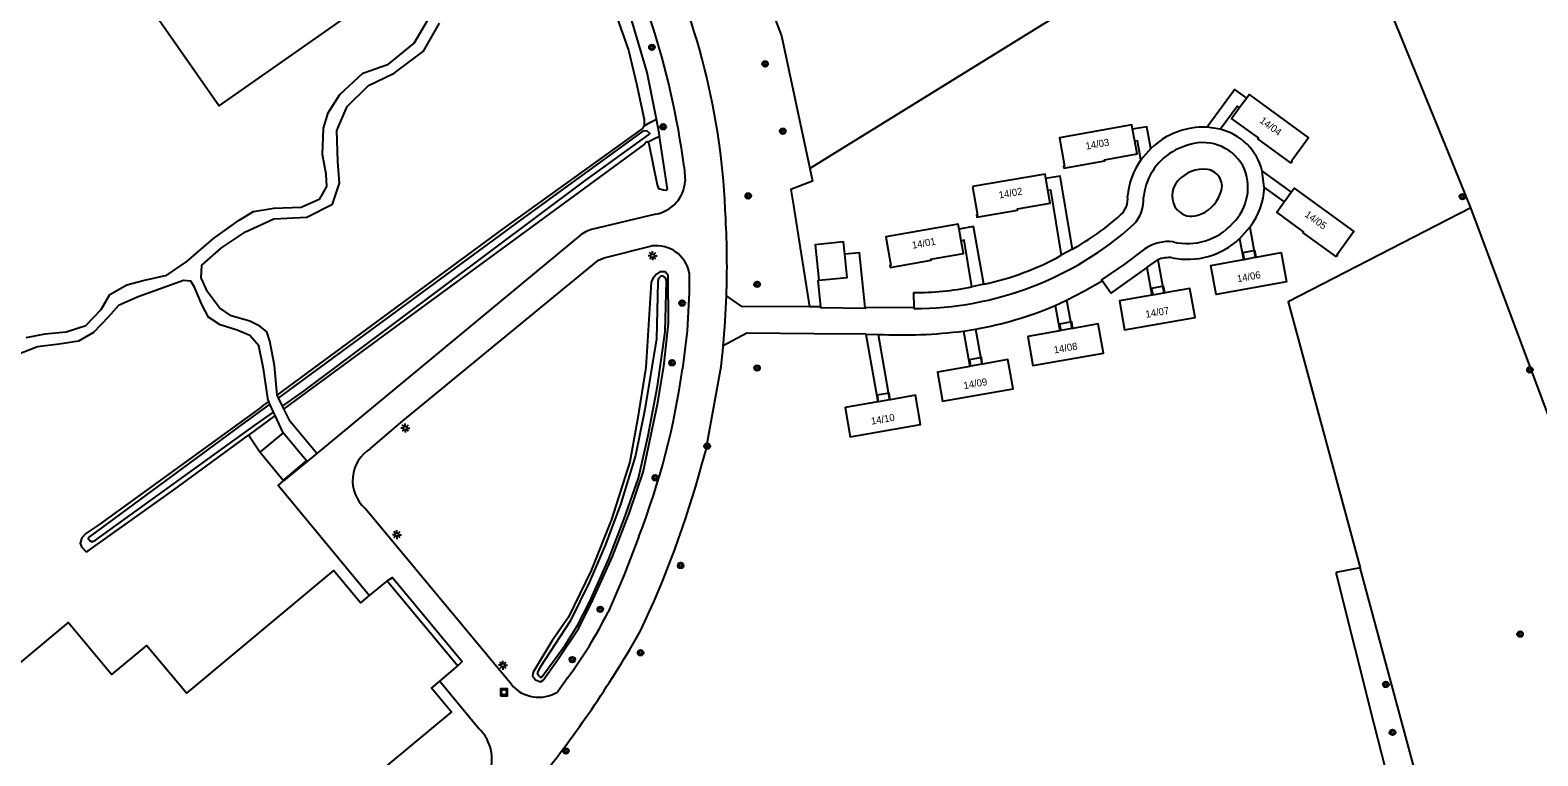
# Model space of a CAD drawing. Extents: x 141000 to 143000, y 400580 to 403500.
# Drawn here: x 141206 to 141417.1, y 402812.9 to 402914.6 of the extents above; entities that cross this region are included whole.
import ezdxf

# ---------------------------------------------------------------- set-up
doc = ezdxf.new("R2010")
doc.units = 0
for name, color, linetype in [('gg-afsc-erfafscheiding', 7, 'Continuous'), ('gg-anno-huisnummerreeks BGT', 7, 'Continuous'), ('gg-bbg-bijgebouw', 7, 'Continuous'), ('gg-bbg-gedigitaliseerde bijgebouw', 7, 'Continuous'), ('gg-bbg-hoofdgebouw', 7, 'Continuous'), ('gg-bbg-luifel en loopbrug', 7, 'Continuous'), ('gg-knt-bronhoudergrens', 7, 'Continuous'), ('gg-knt-onverhard', 7, 'Continuous'), ('gg-knt-verharding', 7, 'Continuous'), ('gg-knt-verharding nz', 7, 'Continuous'), ('gg-kntw-bovenkant insteek waterloop', 7, 'Continuous'), ('gg-kntw-waterlijn', 7, 'Continuous'), ('gt-grn-groengrens', 7, 'Continuous'), ('gt-symb-boom', 7, 'Continuous'), ('gt-symb-lichtmast', 7, 'Continuous'), ('gt-symb-rioolschacht', 7, 'Continuous')]:
    doc.layers.add(name, color=color, linetype=linetype)

# ---------------------------------------------------------------- blocks, each defined once
blk = doc.blocks.new('gt0-BOOM')
at = {"layer": 'gt-symb-boom'}
for radius in [0.4, 0.2]:
    blk.add_circle((0, 0), radius, dxfattribs=at)
blk = doc.blocks.new('gt0-LMAST')
at = {"layer": 'gt-symb-lichtmast'}
for p, q in [((-0.18, 0.17), (-0.45, 0.44)), ((-0.01, 0.25), (-0.01, 0.62)), ((0.17, 0.17), (0.44, 0.44)), ((-0.26, 0), (-0.63, 0)), ((-0.18, -0.18), (-0.45, -0.45)), ((-0.01, -0.25), (-0.01, -0.63)), ((0.44, -0.45), (0.17, -0.18)), ((0.24, 0), (0.62, 0))]:
    blk.add_line(p, q, dxfattribs=at)
blk.add_circle((-0.01, 0), 0.25, dxfattribs=at)
blk = doc.blocks.new('gt0-RS')
at = {"layer": 'gt-symb-rioolschacht'}
blk.add_lwpolyline([(-0.5, -0.5), (0.5, -0.5), (0.5, 0.5), (-0.5, 0.5)], close=True, dxfattribs=at)
blk.add_circle((0, 0), 0.375, dxfattribs=at)

msp = doc.modelspace()

# ---------------------------------------------------------------- linework, layer by layer
at = {"layer": 'gg-afsc-erfafscheiding'}
msp.add_line((141241.49, 402851.46), (141241.44, 402851.52), dxfattribs=at)
at = {"layer": 'gg-bbg-bijgebouw'}
for points in [[(141320.08, 402883.22), (141319.9, 402884.94), (141315.94, 402884.53), (141316.46, 402879.57)], [(141316.46, 402879.57), (141320.42, 402879.98), (141320.08, 402883.22)]]:
    msp.add_lwpolyline(points, dxfattribs=at)
at = {"layer": 'gg-bbg-gedigitaliseerde bijgebouw'}
for p in [(141241.42, 402858.2), (141241.44, 402851.52)]:
    msp.add_line(p, (141238.15, 402855.47), dxfattribs=at)
msp.add_lwpolyline([(141241.44, 402851.52), (141244.72, 402854.25), (141241.42, 402858.2)], dxfattribs=at)
at = {"layer": 'gg-bbg-hoofdgebouw'}
for p, q in [((141375.33, 402903.73), (141376.33, 402905.1)), ((141360.69, 402899.06), (141360.39, 402900.73)), ((141348.52, 402892.19), (141348.24, 402893.83)), ((141381.63, 402890.55), (141382.61, 402891.9)), ((141336.39, 402885.1), (141336.09, 402886.75)), ((141375.91, 402882.49), (141376, 402882.5)), ((141376, 402882.5), (141377.57, 402882.79)), ((141377.57, 402882.79), (141377.68, 402882.81)), ((141363.2, 402877.51), (141363.06, 402877.49)), ((141363.2, 402877.51), (141364.74, 402877.79)), ((141364.74, 402877.79), (141364.88, 402877.81)), ((141350.33, 402872.52), (141350.18, 402872.49)), ((141351.87, 402872.8), (141350.33, 402872.52)), ((141352.02, 402872.82), (141351.87, 402872.8)), ((141337.7, 402867.52), (141337.6, 402867.51)), ((141339.26, 402867.8), (141337.7, 402867.52)), ((141339.38, 402867.82), (141339.26, 402867.8)), ((141324.76, 402862.54), (141324.7, 402862.53)), ((141326.36, 402862.82), (141324.76, 402862.54)), ((141326.45, 402862.84), (141326.36, 402862.82)), ((141256, 402837.47), (141253.46, 402835.38)), ((141256, 402837.47), (141265.92, 402825.53)), ((141263.36, 402823.38), (141265.92, 402825.53))]:
    msp.add_line(p, q, dxfattribs=at)
for points in [[(141376.33, 402905.1), (141376.71, 402905.62), (141385.03, 402899.55), (141382.64, 402896.26), (141382.74, 402896.19), (141382.6, 402895.98)], [(141382.6, 402895.98), (141377.92, 402899.41), (141378.01, 402899.53), (141374.26, 402902.26), (141375.33, 402903.73)], [(141360.39, 402900.73), (141360.27, 402901.37), (141350.13, 402899.55), (141350.85, 402895.55), (141350.72, 402895.53), (141350.77, 402895.28)], [(141350.77, 402895.28), (141356.48, 402896.31), (141356.45, 402896.45), (141361.01, 402897.28), (141360.69, 402899.06)], [(141348.24, 402893.83), (141348.13, 402894.46), (141337.97, 402892.7)], [(141337.97, 402892.7), (141338.65, 402888.7), (141338.53, 402888.68), (141338.57, 402888.43), (141344.29, 402889.42), (141344.27, 402889.57), (141348.83, 402890.36), (141348.52, 402892.19)], [(141382.61, 402891.9), (141383.02, 402892.46), (141391.35, 402886.41), (141388.98, 402883.11), (141389.08, 402883.04), (141388.93, 402882.84)], [(141388.93, 402882.84), (141384.24, 402886.26), (141384.33, 402886.38), (141380.58, 402889.1), (141381.63, 402890.55)], [(141336.09, 402886.75), (141335.97, 402887.44), (141325.83, 402885.65), (141326.53, 402881.65), (141326.41, 402881.63), (141326.45, 402881.38)], [(141326.45, 402881.38), (141332.16, 402882.4), (141332.13, 402882.54), (141336.7, 402883.34), (141336.39, 402885.1)], [(141377.68, 402882.81), (141381.21, 402883.45), (141381.95, 402879.36), (141372.09, 402877.58), (141371.36, 402881.66), (141375.91, 402882.49)], [(141363.06, 402877.49), (141358.55, 402876.69), (141359.27, 402872.61), (141369.14, 402874.35), (141368.42, 402878.43), (141364.88, 402877.81)], [(141350.18, 402872.49), (141345.71, 402871.7), (141346.43, 402867.61), (141356.29, 402869.36), (141355.56, 402873.46), (141352.02, 402872.82)], [(141337.6, 402867.51), (141333.07, 402866.7), (141333.79, 402862.61), (141343.65, 402864.37), (141342.92, 402868.45), (141339.38, 402867.82)], [(141324.7, 402862.53), (141320.12, 402861.73), (141320.84, 402857.64), (141330.7, 402859.36), (141329.98, 402863.46), (141326.45, 402862.84)], [(141253.46, 402835.38), (141252.26, 402834.38), (141248.5, 402838.88), (141227.88, 402821.7), (141222.3, 402828.38), (141217.42, 402824.34), (141211.33, 402831.63), (141190.16, 402813.95), (141190.17, 402813.93)], [(141232.74, 402805.73), (141239.4, 402797.73), (141265, 402819.06), (141262.19, 402822.41), (141263.36, 402823.38)]]:
    msp.add_lwpolyline(points, dxfattribs=at)
at = {"layer": 'gg-bbg-luifel en loopbrug'}
for points in [[(141377.68, 402882.81), (141377.52, 402883.74), (141375.84, 402883.42), (141376, 402882.5)], [(141364.88, 402877.81), (141364.72, 402878.73), (141363.03, 402878.44), (141363.2, 402877.51)], [(141352.02, 402872.82), (141351.86, 402873.75), (141350.17, 402873.44), (141350.33, 402872.52)], [(141339.38, 402867.82), (141339.22, 402868.75), (141337.54, 402868.44), (141337.7, 402867.52)], [(141326.45, 402862.84), (141326.29, 402863.76), (141324.6, 402863.47), (141324.76, 402862.54)]]:
    msp.add_lwpolyline(points, dxfattribs=at)
at = {"layer": 'gg-knt-bronhoudergrens'}
for p, q in [((141404.66, 402897.35), (141387.07, 402940.44)), ((141407.77, 402889.73), (141404.66, 402897.35)), ((141409.82, 402774.28), (141392.26, 402839.26))]:
    msp.add_line(p, q, dxfattribs=at)
for points in [[(141296.65, 402946.16), (141298.25, 402943.84), (141304.41, 402931.66), (141311.24, 402913.82), (141315.18, 402895.24)], [(141386.16, 402940.68), (141374.83, 402932.2), (141315.18, 402895.24)], [(141312.89, 402890.03), (141312.98, 402889.45), (141315.14, 402875.85)], [(141407.77, 402889.73), (141382.18, 402876.56), (141392.26, 402839.26)], [(141432.62, 402827.07), (141427.58, 402836.55), (141407.77, 402889.73)]]:
    msp.add_lwpolyline(points, dxfattribs=at)
at = {"layer": 'gg-knt-onverhard'}
for p, q in [((141300.61, 402855.69), (141302.78, 402867.51)), ((141392.26, 402839.26), (141388.85, 402838.6))]:
    msp.add_line(p, q, dxfattribs=at)
at = {"layer": 'gg-knt-verharding'}
for p, q in [((141372.67, 402900.73), (141370.8, 402901.04)), ((141362.95, 402898.03), (141361.54, 402896.44)), ((141297.57, 402895.47), (141297.74, 402893.47)), ((141378.52, 402894.87), (141382.61, 402891.9)), ((141378.83, 402892.58), (141378.52, 402894.87)), ((141378.83, 402892.58), (141381.63, 402890.55)), ((141375.38, 402885.4), (141376.8, 402887.02)), ((141376.8, 402887.02), (141377.57, 402882.79)), ((141351.99, 402883.95), (141350.4, 402883.08)), ((141375.38, 402885.4), (141375.91, 402882.49)), ((141362.37, 402881.36), (141363.92, 402882.43)), ((141363.92, 402882.43), (141364.74, 402877.79)), ((141362.37, 402881.36), (141363.06, 402877.49)), ((141329.69, 402877.85), (141329.76, 402875.73)), ((141339.54, 402879.02), (141337.89, 402878.65)), ((141316.75, 402875.84), (141315.14, 402875.85)), ((141329.76, 402875.73), (141322.96, 402875.76)), ((141329.76, 402875.61), (141329.76, 402875.73)), ((141349.54, 402876.03), (141350.18, 402872.49)), ((141351.15, 402876.78), (141351.87, 402872.8)), ((141323.04, 402872), (141315.74, 402872.08)), ((141323.04, 402872), (141324.7, 402862.53)), ((141324.75, 402871.99), (141326.36, 402862.82)), ((141336.72, 402872.45), (141337.6, 402867.51)), ((141338.38, 402872.73), (141339.26, 402867.8)), ((141302.78, 402867.51), (141302.95, 402869.27)), ((141239.58, 402862.23), (141239.42, 402862.57)), ((141240.79, 402863.12), (141240.62, 402863.46)), ((141241.35, 402861.95), (141240.79, 402863.12)), ((141240.1, 402861.09), (141239.58, 402862.23)), ((141240.31, 402860.63), (141240.1, 402861.09)), ((141241.42, 402858.2), (141240.31, 402860.63)), ((141241.55, 402861.54), (141241.35, 402861.95)), ((141238.15, 402855.47), (141236.57, 402857.87)), ((141246.13, 402855.3), (141241.49, 402851.46)), ((141300.08, 402853.75), (141300.61, 402855.69)), ((141273.39, 402822.91), (141252.91, 402847.61)), ((141263.36, 402823.38), (141268.9, 402816.72)), ((141281.3, 402823.9), (141279.86, 402821.86))]:
    msp.add_line(p, q, dxfattribs=at)
for points in [[(141205.43, 402871.57), (141208.12, 402872.05), (141211.06, 402872.34), (141213.81, 402873.25), (141215.93, 402875.47), (141217.18, 402877.59), (141219.54, 402878.94), (141221.85, 402879.52), (141225.13, 402880.29), (141227.97, 402882.21), (141231.68, 402885.44), (141235.29, 402887.99), (141237.27, 402889.2), (141240.11, 402889.68), (141243.96, 402889.82), (141246.56, 402890.98), (141247.53, 402892.71), (141247.48, 402894.45), (141246.95, 402897.19), (141247.09, 402900.9), (141247.72, 402903.02), (141249.36, 402905.62), (141252.58, 402908.61), (141256.2, 402909.86), (141259.76, 402912.8), (141261.78, 402916.22)], [(141240.62, 402863.46), (141240.21, 402867.61), (141239.59, 402871.06), (141239.13, 402872.35), (141238.16, 402873.13), (141236.75, 402873.84), (141234.15, 402874.57), (141232.52, 402875.72), (141230.84, 402877.94), (141229.96, 402879.92), (141230.03, 402881.7), (141232.82, 402884.14), (141236.16, 402886.37), (141240.15, 402888.2), (141244.73, 402888.41), (141248.36, 402890.24), (141249.32, 402893.18), (141249.07, 402896.24), (141248.94, 402900.58), (141250.4, 402903.92), (141253.4, 402906.86), (141256.96, 402908.59), (141261.11, 402911.66), (141263.34, 402915.62)], [(141370.8, 402901.04), (141374.66, 402906.31), (141376.33, 402905.1)], [(141372.67, 402900.73), (141375.01, 402903.96), (141375.33, 402903.73)], [(141362.95, 402898.03), (141362.39, 402901.08), (141360.39, 402900.73)], [(141361.54, 402896.44), (141361.08, 402899.13), (141360.69, 402899.06)], [(141351.99, 402883.95), (141350.26, 402894.18), (141348.24, 402893.83)], [(141348.52, 402892.19), (141348.88, 402892.25), (141350.4, 402883.08)], [(141362.28, 402893.01), (141362.04, 402892.04), (141361.93, 402891.24)], [(141293.63, 402888.85), (141284.61, 402886.71), (141283.87, 402886.41), (141283.19, 402885.99), (141246.13, 402855.3)], [(141339.54, 402879.02), (141338.11, 402887.11), (141336.09, 402886.75)], [(141253.67, 402855.98), (141257.91, 402859.65), (141285.61, 402882.37), (141286.37, 402882.74), (141293.08, 402884.38)], [(141337.89, 402878.65), (141336.78, 402885.17), (141336.39, 402885.1)], [(141362.12, 402884), (141359.27, 402881.84), (141356.05, 402879.62), (141356.13, 402879.5)], [(141322.96, 402875.76), (141322.16, 402883.43), (141320.08, 402883.22)], [(141239.42, 402862.57), (141239.34, 402862.74), (141238.69, 402867.15), (141238.02, 402870.38), (141236.75, 402871.85), (141234.98, 402872.58), (141232.62, 402873.34), (141230.97, 402874.42), (141230.05, 402876.19), (141229.01, 402878.6), (141228.49, 402879.43), (141227.5, 402879.54), (141221.12, 402877.26), (141218.4, 402876.05), (141216.92, 402874.42), (141214.9, 402872.24), (141212.76, 402871.05), (141210.05, 402870.62), (141207.05, 402870.26), (141204.04, 402869.07)], [(141298.3, 402880.62), (141298.28, 402877.86), (141298, 402872.5), (141297.38, 402867.16)], [(141316.75, 402875.84), (141316.36, 402879.56), (141316.46, 402879.57)], [(141351.15, 402876.78), (141353.66, 402878.11), (141356.13, 402879.5)], [(141362.37, 402881.36), (141357.33, 402877.75), (141356.13, 402879.5)], [(141315.14, 402875.85), (141305.68, 402875.92), (141303.51, 402877.38)], [(141315.74, 402872.08), (141306.37, 402872.18), (141303.06, 402870.38)], [(141246.13, 402855.3), (141242.4, 402859.79), (141241.55, 402861.54)], [(141253.46, 402835.38), (141240.73, 402850.83), (141241.49, 402851.46)], [(141291.26, 402843.65), (141289.2, 402838.31), (141286.93, 402833.07)], [(141256, 402837.47), (141256.74, 402837.92), (141266.52, 402826.15), (141265.92, 402825.53)]]:
    msp.add_lwpolyline(points, dxfattribs=at)
for centre, radius, start, end in [((141203.51, 402884.91), 99.95, 1.8735, 26.3315), ((141185.61, 402880.89), 112.91, 7.4198, 18.0776), ((141370.39, 402890.36), 10.69, 87.7956, 134.1768), ((141370.8, 402893.01), 7.94, 13.5723, 76.3983), ((141370.2, 402892.34), 6.53, 30.3583, 111.4062), ((141370.38, 402890.33), 10.75, 145.3573, 174.5935), ((141370.33, 402890.31), 8.48, 107.2125, 161.4894), ((141370.29, 402890.42), 4.7, 82.8315, 139.1211), ((141370.57, 402892.77), 2.34, 331.851, 82.5055), ((141369.54, 402892.59), 7, 313.8438, 25.8084), ((141292.73, 402893.79), 5.02, 280.3478, 356.3667), ((141369.01, 402891.41), 3.09, 137.53, 220.2784), ((141368.85, 402893.08), 10, 322.7146, 357.1256), ((141356.82, 402890.93), 2.88, 310.381, 8.2281), ((141356.85, 402890.91), 5.09, 316.1006, 3.6949), ((141368.17, 402893.21), 4.72, 286.7499, 340.8742), ((141184.09, 402881.54), 119.5, 358.0049, 3.1838), ((141335.27, 402914.47), 34.8, 298.7119, 312.3036), ((141368.62, 402891.14), 2.61, 221.2053, 290.3381), ((141329.82, 402921.53), 45.92, 269.9285, 311.9622), ((141368.04, 402893.23), 8.52, 256.6734, 318.1453), ((141293.69, 402879.72), 4.7, 11.0397, 97.4045), ((141365.32, 402879.33), 5.66, 82.2797, 124.4335), ((141368.05, 402893.23), 10.72, 258.6424, 313.1346), ((141331.51, 402917.05), 38.87, 281.9251, 299.0701), ((141365.45, 402878.92), 3.83, 82.6033, 113.474), ((141185.15, 402881.5), 118.43, 354.6093, 358.0048), ((141330.08, 402916.26), 38.41, 269.4172, 281.737), ((141329.7, 402922.6), 50.62, 279.8715, 293.0792), ((141328, 402943.25), 71.34, 267.3911, 277.0211), ((141196.4, 402880.32), 107.13, 354.0791, 354.674), ((141191.02, 402882.28), 107.42, 338.9227, 351.9101), ((141256.39, 402851.51), 5.23, 121.271, 228.2982), ((141164.12, 402890.65), 140.88, 334.6614, 344.8114), ((141230.79, 402861.23), 62.81, 323.5377, 333.3638), ((141153.37, 402909.18), 158.99, 321.5784, 330.2828), ((141277.25, 402826.21), 5.07, 220.5638, 300.9945), ((141264.62, 402812.45), 6.05, 31.9733, 44.8992), ((141264.63, 402812.46), 6.03, 317.9723, 31.9761)]:
    msp.add_arc(centre, radius, start, end, dxfattribs=at)
at = {"layer": 'gg-knt-verharding nz'}
for p, q in [((141349.54, 402876.03), (141351.15, 402876.78)), ((141323.04, 402872), (141324.75, 402871.99)), ((141336.72, 402872.45), (141338.38, 402872.73))]:
    msp.add_line(p, q, dxfattribs=at)
msp.add_lwpolyline([(141322.96, 402875.76), (141322.95, 402875.64), (141316.75, 402875.72), (141316.75, 402875.84)], dxfattribs=at)
at = {"layer": 'gg-kntw-bovenkant insteek waterloop'}
for p, q in [((141238.38, 402861.8), (141239.42, 402862.57)), ((141240.31, 402860.63), (141236.57, 402857.87))]:
    msp.add_line(p, q, dxfattribs=at)
for points in [[(141293.7, 402902.15), (141292.42, 402908.67), (141289.74, 402917.71), (141283.71, 402930.5), (141282.53, 402933.17)], [(141280.92, 402931.17), (141286.21, 402920.81), (141288.18, 402916.46), (141289.81, 402911.82), (141290.94, 402906.92), (141291.99, 402902.11), (141292, 402901.23)], [(141240.62, 402863.46), (141272.25, 402886.76), (141291.81, 402900.83), (141292, 402901.23)], [(141294.15, 402899.73), (141294.08, 402900.21), (141293.7, 402902.15)], [(141292.54, 402898.94), (141292.44, 402898.96), (141292.27, 402898.92), (141292.06, 402898.64), (141259.3, 402874.63), (141241.55, 402861.54)], [(141292.54, 402898.94), (141292.65, 402898.67), (141293.83, 402892.93), (141293.98, 402892.45), (141294.72, 402892.23), (141295.12, 402892.21), (141295.28, 402892.34), (141294.15, 402899.73)], [(141284.85, 402834.87), (141287.54, 402840.86), (141289.93, 402847.05), (141291.85, 402852.69), (141293.85, 402862.22), (141294.76, 402867.48), (141295.42, 402873.57), (141295.35, 402880.25), (141294.92, 402880.77), (141294.2, 402880.75), (141293.71, 402880.41), (141293.2, 402879.82), (141292.99, 402879.31), (141292.24, 402867.34), (141291.07, 402860.05), (141289.96, 402854.12), (141287.4, 402846.05), (141284.59, 402838.91), (141281.39, 402832.38), (141279.08, 402829), (141276.46, 402824.67), (141276.33, 402824.14), (141276.76, 402823.57), (141277.46, 402823.28), (141277.87, 402823.54), (141279.83, 402826.27), (141282.84, 402830.83), (141284.85, 402834.87)], [(141238.38, 402861.8), (141237.81, 402861.38), (141215.63, 402845.32), (141214.65, 402844.66)], [(141214.65, 402844.66), (141213.8, 402844.09), (141213.23, 402843.49), (141213, 402842.74), (141213.2, 402842.21), (141213.86, 402841.54), (141214.13, 402841.65), (141226.14, 402850.19), (141236.57, 402857.87)]]:
    msp.add_lwpolyline(points, dxfattribs=at)
at = {"layer": 'gg-kntw-waterlijn'}
for points in [[(141292, 402901.23), (141292.89, 402901.71), (141293.7, 402902.15)], [(141292.61, 402899.96), (141292.77, 402900.12), (141292.35, 402900.53), (141291.79, 402900.46), (141274.72, 402888.04), (141240.79, 402863.12)], [(141241.35, 402861.95), (141244.4, 402864.08), (141283.69, 402893.51), (141292.61, 402899.96)], [(141294.15, 402899.73), (141293.33, 402899.33), (141292.54, 402898.94)], [(141277.02, 402824.57), (141277.14, 402824.24), (141277.48, 402823.91), (141277.72, 402824.06), (141280.95, 402828.46), (141282.64, 402831.19), (141284.36, 402834.58), (141287.02, 402840.55), (141289.2, 402846.12), (141291.2, 402851.85), (141292.57, 402857.81), (141293.85, 402864.72), (141294.92, 402872.37), (141295.12, 402879.5), (141294.97, 402879.91), (141294.66, 402880.15), (141294.38, 402880.2), (141294.01, 402879.81), (141293.9, 402879.36), (141293.7, 402871.37), (141292.09, 402861.46), (141290.77, 402855.03), (141288.73, 402848.3), (141286.56, 402842.56), (141284.35, 402837.3), (141281.65, 402831.8), (141277.44, 402825.36), (141277.02, 402824.57)], [(141239.58, 402862.23), (141236.18, 402859.74), (141214.36, 402843.65), (141214.12, 402843.4), (141214.4, 402843.07), (141214.66, 402842.94), (141215.18, 402843.15), (141237.74, 402859.44), (141240.1, 402861.09)]]:
    msp.add_lwpolyline(points, dxfattribs=at)
at = {"layer": 'gt-grn-groengrens'}
for points in [[(141212.2, 402933.08), (141232.48, 402904), (141253.94, 402919.11), (141208.64, 402981.64)], [(141315.18, 402895.24), (141315.56, 402893.46), (141312.53, 402892.29), (141312.89, 402890.03)], [(141388.85, 402838.6), (141394.17, 402817.4), (141402.76, 402783.78)]]:
    msp.add_lwpolyline(points, dxfattribs=at)

# ---------------------------------------------------------------- block references
at = {"layer": 'gt-symb-boom'}
for p in [(141293.08, 402912.22), (141308.92, 402909.9), (141294.65, 402901.08), (141311.41, 402900.46), (141306.57, 402891.39), (141406.57, 402891.29), (141307.81, 402879), (141297.31, 402876.37), (141295.89, 402868.02), (141307.8, 402867.28), (141416.03, 402867.01), (141300.81, 402856.34), (141293.54, 402851.9), (141297.1, 402839.62), (141285.84, 402833.46), (141414.65, 402829.99), (141281.93, 402826.41), (141291.49, 402827.38), (141395.86, 402822.94), (141396.78, 402816.22), (141281.02, 402813.61)]:
    msp.add_blockref('gt0-BOOM', p, dxfattribs=at)
at = {"layer": 'gt-symb-lichtmast'}
for p in [(141293.18, 402883.01), (141258.54, 402858.86), (141257.37, 402843.92), (141272.23, 402825.63)]:
    msp.add_blockref('gt0-LMAST', p, dxfattribs=at)
at = {"layer": 'gt-symb-rioolschacht'}
msp.add_blockref('gt0-RS', (141272.35, 402821.84), dxfattribs=at)

# ---------------------------------------------------------------- texts
at = {"layer": 'gg-anno-huisnummerreeks BGT'}
for s, rotation, p in [('14/04', 323.9, (141378.09, 402901.75)), ('14/03', 10.2, (141353.89, 402897.87)), ('14/02', 9.8, (141341.73, 402891.02)), ('14/05', 324, (141384.41, 402888.6)), ('14/01', 10, (141329.58, 402883.98)), ('14/06', 10.3, (141375.1, 402879.29)), ('14/07', 10, (141362.28, 402874.3)), ('14/08', 10.1, (141349.44, 402869.31)), ('14/09', 10.1, (141336.8, 402864.31)), ('14/10', 9.9, (141323.84, 402859.33))]:
    msp.add_text(s, height=1, rotation=rotation, dxfattribs=at).set_placement(p)

doc.saveas('drawing.dxf')
